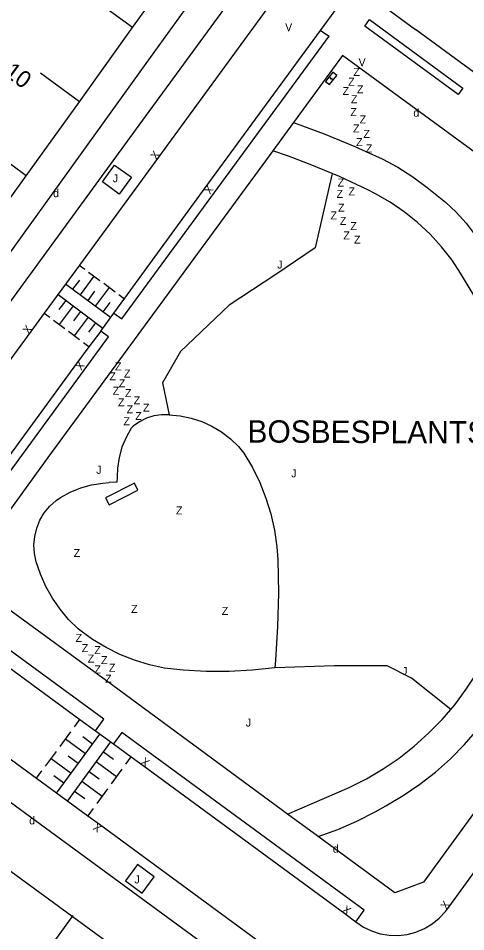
# Model space of a CAD drawing. Extents: x 134999 to 136502, y 457398 to 459002.
# Drawn here: x 135583.3 to 135611.3, y 457653 to 457710.1 of the extents above; entities that cross this region are included whole.
import ezdxf

# ---------------------------------------------------------------- set-up
doc = ezdxf.new("R2010")
doc.units = 0
for name, color, linetype in [('RI_DGTB_15', 7, 'Continuous'), ('RI_DGTB_18', 7, 'Continuous'), ('RI_DGTB_2', 7, 'Continuous'), ('RI_DGTB_29', 7, 'Continuous'), ('RI_DGTB_30', 7, 'Continuous'), ('RI_DGTB_31', 7, 'Continuous'), ('RI_DGTB_32', 7, 'Continuous'), ('RI_DGTB_36', 7, 'Continuous'), ('RI_DGTB_37', 7, 'Continuous'), ('RI_DGTB_53', 7, 'Continuous')]:
    doc.layers.add(name, color=color, linetype=linetype)

msp = doc.modelspace()

# ---------------------------------------------------------------- linework, layer by layer
at = {"layer": 'RI_DGTB_15'}
for p, q in [((135590.458, 457709.479), (135588.039, 457711.254)), ((135587.127, 457704.854), (135584.708, 457706.629)), ((135583.796, 457700.229), (135581.377, 457702.004)), ((135586.727, 457654.003), (135584.952, 457651.585))]:
    msp.add_line(p, q, dxfattribs=at)
at = {"layer": 'RI_DGTB_18'}
for points in [[(135602.923, 457700.365), (135601.878, 457695.73), (135599.416, 457694.063), (135596.49, 457692.131), (135593.456, 457689.253), (135592.324, 457687.282), (135592.739, 457685.279)], [(135610.344, 457666.883), (135607.897, 457668.836), (135606.374, 457669.608), (135603.087, 457669.607), (135599.359, 457669.489)]]:
    msp.add_lwpolyline(points, dxfattribs=at)
at = {"layer": 'RI_DGTB_2'}
msp.add_line((135605.88, 457711.037), (135608.152, 457709.366), dxfattribs=at)
for points in [[(135590.458, 457709.479), (135593.863, 457714.208)], [(135587.127, 457704.854), (135590.458, 457709.479)], [(135638.229, 457696.299), (135633.952, 457690.485), (135628.137, 457694.732), (135608.152, 457709.366)], [(135583.796, 457700.229), (135587.127, 457704.854)], [(135580.464, 457695.603), (135583.796, 457700.229)], [(135582.328, 457657.153), (135586.685, 457653.961)], [(135586.685, 457653.961), (135587.528, 457653.343), (135590.668, 457651.045), (135590.977, 457650.819)]]:
    msp.add_lwpolyline(points, dxfattribs=at)
at = {"layer": 'RI_DGTB_29'}
for points in [[(135602.973, 457706.688), (135602.518, 457706.113), (135602.762, 457705.92), (135603.217, 457706.495), (135602.973, 457706.688)], [(135602.791, 457706.423), (135602.839, 457706.268), (135602.896, 457706.34), (135602.944, 457706.185)]]:
    msp.add_lwpolyline(points, dxfattribs=at)
at = {"layer": 'RI_DGTB_31'}
for p, q in [((135587.12, 457694.642), (135587.474, 457694.38)), ((135587.709, 457694.205), (135588.415, 457693.681)), ((135586.728, 457693.131), (135587.16, 457693.712)), ((135587.2, 457692.781), (135588.062, 457693.943)), ((135586.258, 457693.48), (135589.084, 457691.383)), ((135588.142, 457692.082), (135589.004, 457693.244)), ((135588.651, 457693.506), (135589.357, 457692.982)), ((135588.602, 457690.691), (135585.81, 457692.792)), ((135587.67, 457692.432), (135588.102, 457693.013)), ((135589.593, 457692.807), (135589.946, 457692.545)), ((135586.276, 457692.441), (135585.839, 457691.86)), ((135586.741, 457692.091), (135585.866, 457690.929)), ((135588.612, 457691.733), (135589.044, 457692.314)), ((135585.285, 457691.366), (135584.935, 457691.629)), ((135587.206, 457691.741), (135586.769, 457691.16)), ((135587.671, 457691.391), (135586.796, 457690.229)), ((135586.215, 457690.666), (135585.517, 457691.191)), ((135588.137, 457691.041), (135587.7, 457690.46)), ((135587.146, 457689.966), (135586.448, 457690.491)), ((135587.727, 457689.528), (135587.378, 457689.791)), ((135586.823, 457665.794), (135587.161, 457666.253)), ((135585.704, 457661.659), (135588.411, 457665.332)), ((135585.92, 457664.57), (135586.597, 457665.488)), ((135587.96, 457664.72), (135587.335, 457665.181)), ((135587.508, 457664.107), (135586.258, 457665.029)), ((135589.082, 457664.854), (135586.381, 457661.166)), ((135585.017, 457663.345), (135585.694, 457664.263)), ((135587.058, 457663.496), (135586.432, 457663.957)), ((135588.632, 457664.24), (135589.269, 457663.773)), ((135590.355, 457663.922), (135590.018, 457663.461)), ((135586.606, 457662.883), (135585.356, 457663.804)), ((135588.182, 457663.625), (135589.455, 457662.692)), ((135584.453, 457662.58), (135584.792, 457663.039)), ((135587.732, 457663.01), (135588.368, 457662.544)), ((135589.793, 457663.154), (135589.118, 457662.232)), ((135586.155, 457662.27), (135585.529, 457662.731)), ((135587.281, 457662.395), (135588.554, 457661.463)), ((135586.831, 457661.781), (135587.468, 457661.314)), ((135588.892, 457661.924), (135588.216, 457661.001)), ((135587.991, 457660.694), (135587.654, 457660.233))]:
    msp.add_line(p, q, dxfattribs=at)
at = {"layer": 'RI_DGTB_32'}
msp.add_lwpolyline([(135588.997, 457679.667), (135590.793, 457680.585), (135590.566, 457681.03), (135588.77, 457680.112), (135588.997, 457679.667)], dxfattribs=at)
at = {"layer": 'RI_DGTB_53'}
for p, q in [((135602.214, 457709.307), (135603.343, 457710.857)), ((135600.201, 457701.446), (135599.22, 457701.775)), ((135588.465, 457690.513), (135589.283, 457691.644)), ((135588.143, 457665.552), (135589.267, 457664.729)), ((135600.131, 457660.341), (135604.003, 457662.013))]:
    msp.add_line(p, q, dxfattribs=at)
for points in [[(135570.74, 457681.671), (135572.151, 457680.619), (135579.561, 457690.924), (135591.312, 457707.234), (135595.636, 457713.263), (135594.205, 457714.255)], [(135576.442, 457680.09), (135574.715, 457681.365), (135581.262, 457690.255), (135590.871, 457703.393), (135597.463, 457712.419), (135599.203, 457711.143)], [(135599.203, 457711.143), (135592.077, 457701.389), (135587.129, 457694.635)], [(135610.813, 457705.299), (135604.975, 457709.578), (135605.27, 457709.98), (135611.107, 457705.701), (135610.813, 457705.299)], [(135589.972, 457692.588), (135594.998, 457699.476), (135602.214, 457709.307)], [(135602.214, 457709.307), (135602.736, 457708.945)], [(135589.283, 457691.644), (135589.788, 457691.297), (135602.736, 457708.945)], [(135631.51, 457687.308), (135616.168, 457698.54), (135603.586, 457707.73), (135600.517, 457703.553)], [(135600.517, 457703.553), (135599.22, 457701.775)], [(135600.517, 457703.553), (135602.443, 457702.837), (135604.341, 457702.047), (135605.044, 457701.732)], [(135599.22, 457701.775), (135585.158, 457682.623), (135580.732, 457676.55), (135580.673, 457674.604)], [(135605.044, 457701.732), (135606.058, 457701.278), (135607.036, 457700.752), (135607.973, 457700.157), (135608.865, 457699.496), (135609.283, 457699.151)], [(135602.923, 457700.365), (135601.564, 457700.932), (135600.201, 457701.446)], [(135590.393, 457700.129), (135589.627, 457699.072), (135588.569, 457699.838), (135589.335, 457700.895), (135590.393, 457700.129)], [(135605.168, 457699.342), (135603.382, 457700.174), (135602.923, 457700.365)], [(135610.434, 457694.948), (135609.773, 457695.784), (135609.051, 457696.568), (135608.272, 457697.296), (135607.441, 457697.963), (135606.563, 457698.566), (135605.642, 457699.101), (135605.168, 457699.342)], [(135609.283, 457699.151), (135610.014, 457698.578), (135610.692, 457697.945), (135611.314, 457697.256), (135611.873, 457696.516), (135612.046, 457696.258)], [(135612.948, 457671.011), (135613.455, 457672.337), (135613.887, 457673.689), (135614.241, 457675.064), (135614.518, 457676.456), (135614.716, 457677.861), (135614.834, 457679.276), (135614.873, 457680.695), (135614.831, 457682.114), (135614.71, 457683.528), (135614.509, 457684.933), (135614.229, 457686.325), (135613.872, 457687.698), (135613.437, 457689.049), (135612.927, 457690.374), (135612.344, 457691.668), (135611.688, 457692.927), (135610.963, 457694.147), (135610.434, 457694.948)], [(135587.129, 457694.635), (135584.93, 457691.633)], [(135589.283, 457691.644), (135589.972, 457692.588)], [(135584.93, 457691.633), (135584.099, 457690.499), (135576.442, 457680.09)], [(135580.536, 457679.73), (135581.035, 457679.36), (135588.95, 457690.169), (135588.465, 457690.513)], [(135588.465, 457690.513), (135587.727, 457689.528)], [(135587.727, 457689.528), (135586.949, 457688.488), (135580.536, 457679.73)], [(135592.739, 457685.279), (135592.256, 457685.291), (135591.777, 457685.224), (135591.316, 457685.078), (135590.885, 457684.859), (135590.496, 457684.571), (135590.372, 457684.456)], [(135592.739, 457685.279), (135593.435, 457685.221), (135594.119, 457685.084), (135594.784, 457684.87), (135595.419, 457684.582), (135596.018, 457684.222), (135596.571, 457683.797), (135597.072, 457683.311), (135597.419, 457682.899)], [(135590.372, 457684.456), (135590.045, 457683.877), (135589.79, 457683.263), (135589.611, 457682.622), (135589.51, 457681.965), (135589.486, 457681.425)], [(135597.419, 457682.899), (135597.946, 457681.999), (135598.402, 457681.062), (135598.784, 457680.092), (135599.092, 457679.096), (135599.322, 457678.08), (135599.473, 457677.048), (135599.536, 457676.246)], [(135585.939, 457680.118), (135586.559, 457680.457), (135587.213, 457680.724), (135587.894, 457680.915), (135588.592, 457681.028), (135588.984, 457681.057)], [(135589.486, 457681.425), (135589.468, 457681.085), (135588.984, 457681.057)], [(135584.435, 457676.114), (135584.323, 457676.635), (135584.29, 457677.166), (135584.337, 457677.697), (135584.462, 457678.214), (135584.664, 457678.707), (135584.937, 457679.164), (135585.276, 457679.575), (135585.672, 457679.931), (135585.939, 457680.118)], [(135587.058, 457671.92), (135586.459, 457672.505), (135585.919, 457673.144), (135585.442, 457673.831), (135585.033, 457674.561), (135584.696, 457675.326), (135584.435, 457676.114)], [(135599.536, 457676.246), (135599.57, 457674.151), (135599.524, 457672.057), (135599.399, 457669.966), (135599.359, 457669.489)], [(135600.131, 457660.341), (135588.821, 457668.666), (135580.673, 457674.604)], [(135588.143, 457665.552), (135588.657, 457666.281), (135580.368, 457672.344)], [(135592.46, 457669.466), (135591.507, 457669.675), (135590.574, 457669.961), (135589.668, 457670.322), (135588.794, 457670.757), (135587.959, 457671.262), (135587.168, 457671.833), (135587.058, 457671.92)], [(135579.848, 457671.614), (135580.434, 457671.192), (135587.162, 457666.254)], [(135610.344, 457666.883), (135610.593, 457667.174), (135611.315, 457668.14), (135611.971, 457669.153), (135612.558, 457670.206), (135612.948, 457671.011)], [(135573.326, 457670.707), (135573.568, 457670.53), (135577.727, 457667.496), (135584.456, 457662.583)], [(135599.359, 457669.489), (135597.931, 457669.332), (135596.497, 457669.254), (135595.06, 457669.257), (135593.626, 457669.34), (135592.46, 457669.466)], [(135572.045, 457668.983), (135573.053, 457668.229), (135599.683, 457648.731), (135600.98, 457650.462)], [(135606.294, 457660.87), (135607.371, 457661.504), (135608.404, 457662.205), (135609.39, 457662.972), (135610.325, 457663.799), (135611.206, 457664.685), (135612.027, 457665.626), (135612.787, 457666.617), (135613.482, 457667.655), (135613.486, 457667.66)], [(135604.003, 457662.013), (135605.081, 457662.554), (135606.121, 457663.166), (135607.118, 457663.845), (135608.067, 457664.589), (135608.966, 457665.394), (135609.809, 457666.257), (135610.344, 457666.883)], [(135587.162, 457666.254), (135588.143, 457665.552)], [(135589.787, 457665.441), (135589.267, 457664.729)], [(135604.411, 457653.605), (135604.938, 457654.338), (135589.787, 457665.441)], [(135589.267, 457664.729), (135590.359, 457663.927)], [(135590.359, 457663.927), (135591.114, 457663.372), (135603.719, 457654.142), (135604.411, 457653.605)], [(135584.456, 457662.583), (135587.661, 457660.242)], [(135602.059, 457658.953), (135603.278, 457659.391), (135604.469, 457659.904), (135605.625, 457660.489), (135606.294, 457660.87)], [(135612.107, 457660.85), (135608.652, 457656.093), (135606.845, 457655.432), (135602.059, 457658.953)], [(135587.661, 457660.242), (135588.382, 457659.715), (135600.881, 457650.535), (135600.98, 457650.462)], [(135602.059, 457658.953), (135600.131, 457660.341)], [(135591.809, 457656.432), (135590.756, 457657.202), (135590.01, 457656.18), (135591.062, 457655.41), (135591.809, 457656.432)], [(135610.082, 457654.341), (135610.22, 457654.538), (135612.104, 457657.121)], [(135604.411, 457653.605), (135604.882, 457653.289), (135605.394, 457653.043), (135605.935, 457652.872), (135606.494, 457652.778), (135607.061, 457652.763), (135607.625, 457652.828), (135608.174, 457652.972), (135608.697, 457653.192), (135609.185, 457653.483), (135609.626, 457653.839), (135610.014, 457654.254), (135610.082, 457654.341)]]:
    msp.add_lwpolyline(points, dxfattribs=at)

# ---------------------------------------------------------------- texts
at = {"layer": 'RI_DGTB_29'}
for p in [(135608.009, 457703.916), (135585.482, 457698.888), (135583.989, 457659.701), (135602.975, 457657.935)]:
    msp.add_text('d', height=0.5, dxfattribs=at).set_placement(p)
at = {"layer": 'RI_DGTB_30'}
for p in [(135599.992, 457709.255), (135604.581, 457707.067)]:
    msp.add_text('V', height=0.5, dxfattribs=at).set_placement(p)
for rotation, p in [(53.8526, (135591.93, 457701.187)), (233.8784, (135595.145, 457699.678)), (53.7703, (135583.951, 457690.297)), (233.1893, (135587.099, 457688.688)), (323.7061, (135590.913, 457663.52)), (143.8615, (135588.584, 457659.568)), (54.9761, (135610.077, 457654.333)), (323.7852, (135603.517, 457654.29))]:
    msp.add_text('X', height=0.5, rotation=rotation, dxfattribs=at).set_placement(p)
at = {"layer": 'RI_DGTB_31'}
for p in [(135589.21, 457699.816), (135599.499, 457694.43), (135588.182, 457681.605), (135600.373, 457681.382), (135607.299, 457669.038), (135597.532, 457665.814), (135590.57, 457656.015)]:
    msp.add_text('J', height=0.5, dxfattribs=at).set_placement(p)
at = {"layer": 'RI_DGTB_32'}
for p in [(135604.261, 457706.466), (135603.933, 457705.844), (135603.584, 457705.272), (135604.48, 457705.373), (135604.105, 457704.76), (135604.067, 457703.953), (135604.647, 457703.492), (135604.242, 457702.935), (135604.886, 457702.593), (135604.429, 457702.078), (135605.038, 457701.682), (135603.271, 457699.549), (135603.204, 457698.843), (135603.954, 457698.995), (135603.305, 457697.985), (135602.828, 457697.493), (135603.415, 457697.159), (135604.068, 457696.831), (135603.631, 457696.244), (135604.298, 457695.984), (135589.357, 457688.064), (135589.007, 457687.444), (135589.912, 457687.617), (135589.593, 457687.009), (135589.215, 457686.54), (135589.978, 457686.397), (135589.543, 457685.818), (135590.524, 457685.942), (135590.079, 457685.38), (135591.109, 457685.49), (135589.883, 457684.64), (135590.621, 457684.968), (135593.167, 457679.067), (135586.772, 457676.407), (135590.362, 457672.913), (135596.029, 457672.789), (135586.892, 457671.102), (135587.279, 457670.468), (135588.061, 457670.342), (135587.648, 457669.813), (135588.481, 457669.712), (135588.066, 457669.129), (135588.974, 457669.238), (135588.74, 457668.555)]:
    msp.add_text('Z', height=0.5, dxfattribs=at).set_placement(p)
at = {"layer": 'RI_DGTB_36'}
msp.add_text('10', height=1.054, rotation=323.7417, dxfattribs=at).set_placement((135582.366, 457706.54))
at = {"layer": 'RI_DGTB_37'}
msp.add_text('BOSBESPLANTSOEN', height=1.4, rotation=359.7566, dxfattribs=at).set_placement((135597.635, 457683.556))

doc.saveas('drawing.dxf')
